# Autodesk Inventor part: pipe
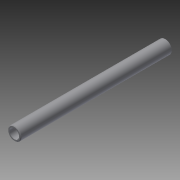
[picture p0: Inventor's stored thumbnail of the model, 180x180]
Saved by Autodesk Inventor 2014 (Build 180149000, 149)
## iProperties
Created: 2004-05
Part Number: pipe
Document SubType Name: Modeling
Designer: dayb
Manufacturer: Standard
Standards Organization: Custom
Density: 1 g/cm^3
Material: Generic
Appearance: Default
Author: dayb
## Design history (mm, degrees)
sketch "Sketch1"
  geometry: C1 r 16.701 at (0, 0); C2 r 12.154 at (0, 0)
  constraints: 2 centre point, 1 coincident
  dimensions: "d0" = 24.3078 diameter of C2 (= ID); "d1" = 33.401 diameter of C1 (= OD)
extrude "Extrusion1" new body sketch "Sketch1" distance "d2" = 381 (= PL); taper "d3" = 0 deg
chamfer "Chamfer1" distance "d4" = 1.51553 (= t); stored, may be unused: second distance "d5" = 3.175, angle "d6" = 45 deg
body "Solid1"
other parameters: "OD" = 33.401 [user parameter; used in 2 equation terms], "ID" = 24.3078 [user parameter; used in 2 equation terms], "PL" = 381 [user parameter; used in 1 equation term], "t" = 1.51553 (= -0.166667 x ID + 0.166667 x OD) [user parameter; used in 1 equation term]
